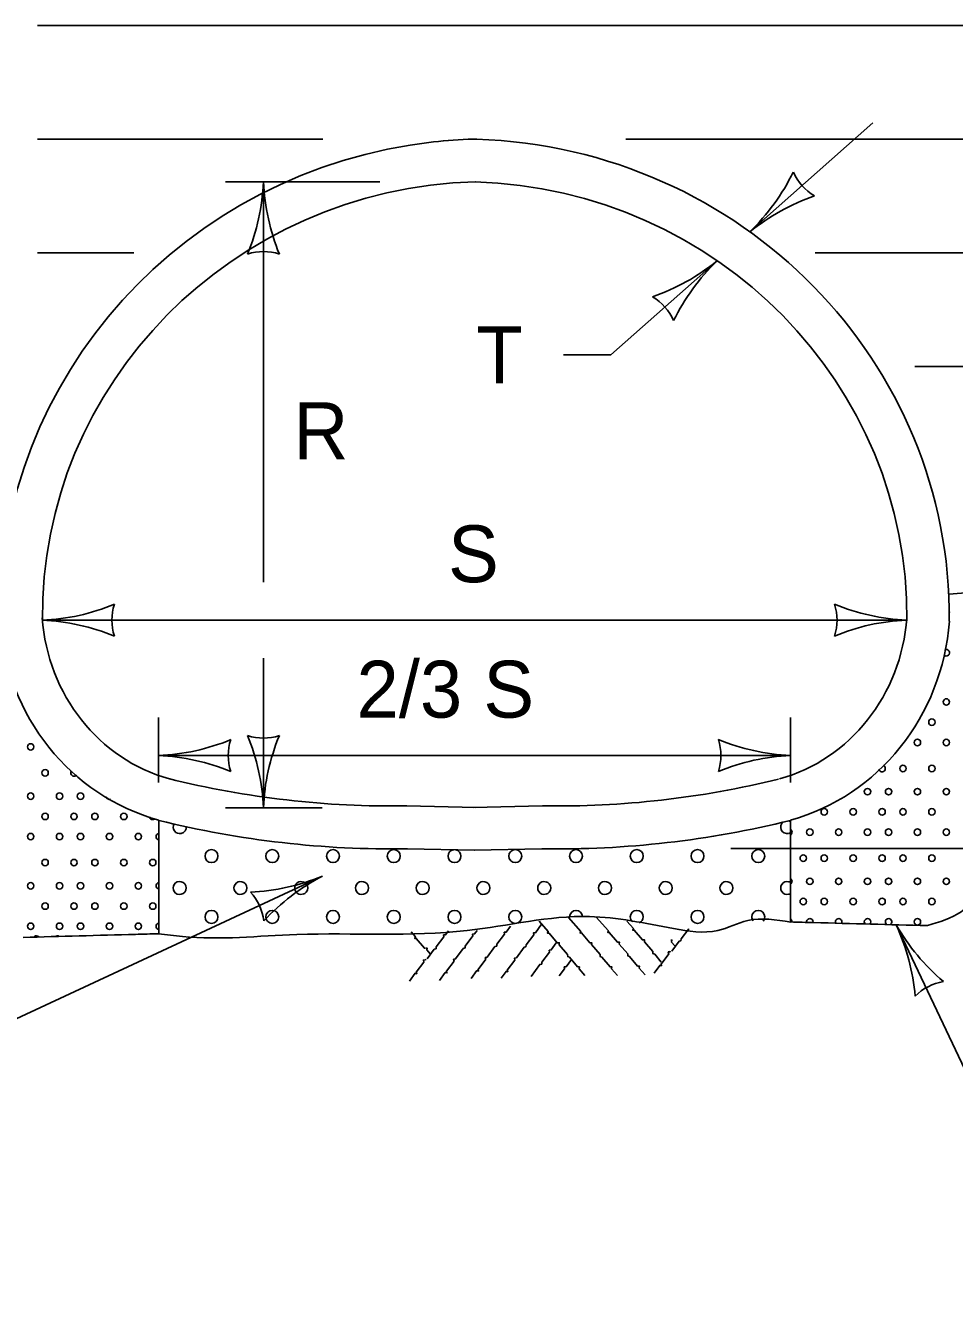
# Model space of a CAD drawing. Extents: x 49991.4 to 50021, y 49987.6 to 50011.4.
# Drawn here: x 50008.772 to 50009.753, y 49996.176 to 49997.512 of the extents above; entities that cross this region are included whole.
import ezdxf

# ---------------------------------------------------------------- set-up
doc = ezdxf.new("R2010")
doc.units = 0
for name, color, linetype in [('Level 1', 7, 'Continuous'), ('Level 2', 7, 'Continuous'), ('Level 3', 7, 'Continuous')]:
    doc.layers.add(name, color=color, linetype=linetype)

msp = doc.modelspace()

# ---------------------------------------------------------------- linework, layer by layer
at = {"layer": 'Level 1'}
for p, q in [((50008.785, 49997.5118), (50010.5816, 49997.5118)), ((50008.785, 49997.3918), (50009.0861, 49997.3918)), ((50009.2483, 49997.3918), (50009.2444, 49997.3918)), ((50009.4058, 49997.3918), (50010.4198, 49997.3918)), ((50008.785, 49997.2718), (50008.8867, 49997.2718)), ((50009.6053, 49997.2718), (50010.2692, 49997.2718)), ((50009.7106, 49997.1518), (50010.1883, 49997.1518)), ((50009.1745, 49996.6886), (50009.2473, 49996.6868)), ((50009.3179, 49996.6886), (50009.2445, 49996.6868)), ((50008.9129, 49996.6735), (50008.9129, 49996.5537)), ((50009.5793, 49996.6735), (50009.5793, 49996.5661)), ((50009.1751, 49996.6432), (50009.2462, 49996.6418)), ((50009.317, 49996.6432), (50009.2456, 49996.6418))]:
    msp.add_line(p, q, dxfattribs=at)
for points in [[(50009.3743, 49996.5712), (50009.3872, 49996.5567), (50009.3865, 49996.5551), (50009.3881, 49996.5551), (50009.3968, 49996.5448), (50009.3989, 49996.5449), (50009.3987, 49996.5428), (50009.4077, 49996.5324), (50009.4077, 49996.5304), (50009.4096, 49996.5298), (50009.4181, 49996.5194), (50009.4202, 49996.5194), (50009.4199, 49996.5173), (50009.426, 49996.5103)], [(50009.2425, 49996.5063), (50009.2485, 49996.5147), (50009.2502, 49996.5143), (50009.2498, 49996.5159), (50009.2579, 49996.5267), (50009.2574, 49996.5287), (50009.2594, 49996.529), (50009.2675, 49996.5401), (50009.2695, 49996.5406), (50009.2697, 49996.5426), (50009.2778, 49996.5532), (50009.2774, 49996.5552), (50009.2795, 49996.5553), (50009.2839, 49996.5615)], [(50009.2741, 49996.5067), (50009.2793, 49996.5139), (50009.281, 49996.5136), (50009.2806, 49996.5151), (50009.2887, 49996.5259), (50009.2882, 49996.528), (50009.2902, 49996.5283), (50009.2983, 49996.5393), (50009.3003, 49996.5399), (50009.3005, 49996.5418), (50009.3086, 49996.5525), (50009.3082, 49996.5545), (50009.3103, 49996.5546), (50009.3168, 49996.5636)], [(50009.3142, 49996.5668), (50009.3238, 49996.556), (50009.323, 49996.5543), (50009.3246, 49996.5544), (50009.3333, 49996.5441), (50009.3354, 49996.5441), (50009.3352, 49996.5421), (50009.3442, 49996.5317), (50009.3443, 49996.5296), (50009.3461, 49996.529), (50009.3547, 49996.5187), (50009.3567, 49996.5186), (50009.3564, 49996.5166), (50009.3625, 49996.5096)], [(50009.3451, 49996.5707), (50009.3581, 49996.556), (50009.3573, 49996.5544), (50009.3589, 49996.5545), (50009.3676, 49996.5441), (50009.3697, 49996.5442), (50009.3695, 49996.5422), (50009.3785, 49996.5317), (50009.3785, 49996.5297), (50009.3804, 49996.5291), (50009.389, 49996.5187), (50009.391, 49996.5187), (50009.3906, 49996.5167), (50009.3968, 49996.5096)], [(50009.4067, 49996.5669), (50009.4137, 49996.5591), (50009.4129, 49996.5574), (50009.4145, 49996.5575), (50009.4232, 49996.5472), (50009.4254, 49996.5472), (50009.4252, 49996.5452), (50009.4341, 49996.5348), (50009.4342, 49996.5327), (50009.4361, 49996.5321), (50009.4431, 49996.5236)], [(50009.4542, 49996.5354), (50009.4618, 49996.5457), (50009.4637, 49996.5463), (50009.4639, 49996.5483), (50009.472, 49996.5589), (50009.472, 49996.5589)], [(50009.179, 49996.5557), (50009.1837, 49996.5503), (50009.183, 49996.5487), (50009.1846, 49996.5487), (50009.1932, 49996.5384), (50009.1943, 49996.5385)], [(50009.1959, 49996.527), (50009.2035, 49996.5373), (50009.2055, 49996.5378), (50009.2057, 49996.5398), (50009.2138, 49996.5505), (50009.2134, 49996.5524), (50009.2155, 49996.5526), (50009.2186, 49996.5568)], [(50009.2091, 49996.5044), (50009.2151, 49996.5128), (50009.2169, 49996.5124), (50009.2165, 49996.514), (50009.2245, 49996.5247), (50009.224, 49996.5268), (50009.226, 49996.5271), (50009.2342, 49996.5382), (50009.2361, 49996.5387), (50009.2363, 49996.5407), (50009.2444, 49996.5513), (50009.244, 49996.5533), (50009.2461, 49996.5535), (50009.2488, 49996.5572)], [(50009.4532, 49996.5469), (50009.4542, 49996.5469), (50009.454, 49996.5449), (50009.4574, 49996.541)], [(50009.1949, 49996.5385), (50009.196, 49996.5385), (50009.1958, 49996.5365), (50009.1991, 49996.5326)], [(50009.3057, 49996.5087), (50009.3149, 49996.5212), (50009.3169, 49996.5217), (50009.3171, 49996.5237), (50009.3252, 49996.5343), (50009.3248, 49996.5363), (50009.3269, 49996.5365), (50009.3323, 49996.5439)], [(50009.4356, 49996.5121), (50009.4415, 49996.5203), (50009.4433, 49996.52), (50009.4429, 49996.5215), (50009.451, 49996.5323), (50009.4504, 49996.5344), (50009.4524, 49996.5347), (50009.4529, 49996.5354)], [(50009.1774, 49996.5036), (50009.1833, 49996.5119), (50009.185, 49996.5115), (50009.1846, 49996.5131), (50009.1927, 49996.5238), (50009.1921, 49996.5259), (50009.1942, 49996.5262), (50009.1947, 49996.5269)], [(50009.3353, 49996.5091), (50009.341, 49996.5167), (50009.3407, 49996.5187), (50009.3427, 49996.5188), (50009.3483, 49996.5265)]]:
    msp.add_lwpolyline(points, dxfattribs=at)
for centre in [(50009.7438, 49996.7981), (50009.7286, 49996.7768), (50009.7286, 49996.7768), (50009.7133, 49996.7554), (50009.7438, 49996.7554), (50008.7777, 49996.7507), (50009.6607, 49996.7035), (50009.6829, 49996.7035), (50009.7133, 49996.7035), (50009.7438, 49996.7035), (50008.7777, 49996.6988), (50008.8082, 49996.6988), (50008.8303, 49996.6988), (50008.7929, 49996.6774), (50008.7929, 49996.6774), (50008.8234, 49996.6774), (50008.8455, 49996.6774), (50008.876, 49996.6774), (50008.876, 49996.6774), (50009.615, 49996.6822), (50009.6455, 49996.6822), (50009.6455, 49996.6822), (50009.676, 49996.6822), (50009.6981, 49996.6822), (50009.7286, 49996.6822), (50009.7286, 49996.6822), (50009.5998, 49996.6608), (50009.6302, 49996.6608), (50009.6607, 49996.6608), (50009.6829, 49996.6608), (50009.7133, 49996.6608), (50009.7438, 49996.6608), (50008.7777, 49996.6561), (50008.8082, 49996.6561), (50008.8303, 49996.6561), (50008.8608, 49996.6561), (50008.8913, 49996.6561), (50009.5998, 49996.6089), (50009.6302, 49996.6089), (50009.6607, 49996.6089), (50009.6829, 49996.6089), (50009.7133, 49996.6089), (50009.7438, 49996.6089), (50008.7777, 49996.6042), (50008.8082, 49996.6042), (50008.8303, 49996.6042), (50008.8608, 49996.6042), (50008.8913, 49996.6042), (50008.7929, 49996.5828), (50008.7929, 49996.5828), (50008.8234, 49996.5828), (50008.8455, 49996.5828), (50008.876, 49996.5828), (50008.876, 49996.5828), (50008.9065, 49996.5828), (50009.5929, 49996.5876), (50009.615, 49996.5876), (50009.6455, 49996.5876), (50009.6455, 49996.5876), (50009.676, 49996.5876), (50009.6981, 49996.5876), (50009.7286, 49996.5876), (50009.7286, 49996.5876), (50008.7777, 49996.5615), (50008.8082, 49996.5615), (50008.8303, 49996.5615), (50008.8608, 49996.5615), (50008.8913, 49996.5615), (50009.7133, 49996.5662)]:
    msp.add_circle(centre, 0.00341, dxfattribs=at)
for centre, radius, start, end in [((50009.7438, 49996.8927), 0.00341, 337.7419, 24.4716), ((50009.7438, 49996.85), 0.00341, 225.166, 117.2024), ((50009.676, 49996.728), 0.00341, 0, 71.4249), ((50009.6981, 49996.728), 0.00341, 0, 180), ((50009.7286, 49996.728), 0.00341, 0, 180), ((50008.7929, 49996.7233), 0.00341, 0, 180), ((50008.7929, 49996.7232), 0.00341, 180, 0), ((50008.7929, 49996.7232), 0.00341, 180, 0), ((50008.8234, 49996.7233), 0.00341, 139.8568, 180), ((50008.8234, 49996.7232), 0.00341, 180, 321.6476), ((50009.676, 49996.7279), 0.00341, 194.081, 0), ((50009.6981, 49996.7279), 0.00341, 180, 0), ((50009.7286, 49996.7279), 0.00341, 180, 0), ((50009.7286, 49996.7279), 0.00341, 180, 0), ((50008.8608, 49996.6988), 0.00341, 190.2156, 289.4106), ((50008.9065, 49996.6774), 0.00341, 185.7827, 313.6596), ((50008.9349, 49996.666), 0.00682, 148.621, 282.921), ((50008.935, 49996.666), 0.00682, 282.921, 6.0281), ((50009.5759, 49996.666), 0.00682, 124.2955, 282.921), ((50009.5759, 49996.666), 0.00682, 77.079, 79.4798), ((50009.576, 49996.666), 0.00682, 60.5066, 77.079), ((50008.9134, 49996.6561), 0.00341, 99.1328, 260.8672), ((50009.576, 49996.666), 0.00682, 282.921, 299.4934), ((50009.5776, 49996.6608), 0.00341, 300.0634, 59.9366), ((50008.9685, 49996.6355), 0.00682, 0, 180), ((50009.0326, 49996.6355), 0.00682, 0, 180), ((50009.0967, 49996.6355), 0.00682, 0, 180), ((50009.1608, 49996.6355), 0.00682, 0, 180), ((50009.2249, 49996.6355), 0.00682, 100.2114, 180), ((50009.2249, 49996.6355), 0.00682, 0, 77.4448), ((50009.289, 49996.6355), 0.00682, 0, 180), ((50009.3531, 49996.6355), 0.00682, 0, 180), ((50009.4172, 49996.6355), 0.00682, 0, 180), ((50009.4813, 49996.6355), 0.00682, 0, 180), ((50009.5454, 49996.6355), 0.00682, 0, 180), ((50008.7929, 49996.6287), 0.00341, 0, 180), ((50008.7929, 49996.6286), 0.00341, 180, 0), ((50008.7929, 49996.6286), 0.00341, 180, 0), ((50008.8234, 49996.6287), 0.00341, 0, 180), ((50008.8234, 49996.6286), 0.00341, 180, 0), ((50008.8455, 49996.6287), 0.00341, 0, 180), ((50008.8455, 49996.6286), 0.00341, 180, 0), ((50008.876, 49996.6287), 0.00341, 0, 180), ((50008.876, 49996.6286), 0.00341, 180, 0), ((50008.876, 49996.6286), 0.00341, 180, 0), ((50008.9065, 49996.6287), 0.00341, 0, 180), ((50008.9065, 49996.6286), 0.00341, 180, 0), ((50008.9685, 49996.6355), 0.00682, 180, 0), ((50009.0326, 49996.6355), 0.00682, 180, 0), ((50009.0967, 49996.6355), 0.00682, 180, 0), ((50009.1608, 49996.6355), 0.00682, 180, 0), ((50009.2249, 49996.6355), 0.00682, 180, 0), ((50009.289, 49996.6355), 0.00682, 180, 0), ((50009.3531, 49996.6355), 0.00682, 180, 0), ((50009.4172, 49996.6355), 0.00682, 180, 0), ((50009.4813, 49996.6355), 0.00682, 180, 0), ((50009.5454, 49996.6355), 0.00682, 180, 0), ((50009.5929, 49996.6334), 0.00341, 0, 180), ((50009.5929, 49996.6333), 0.00341, 180, 0), ((50009.615, 49996.6334), 0.00341, 0, 180), ((50009.615, 49996.6333), 0.00341, 180, 0), ((50009.6455, 49996.6334), 0.00341, 0, 180), ((50009.6455, 49996.6333), 0.00341, 180, 0), ((50009.6455, 49996.6333), 0.00341, 180, 0), ((50009.676, 49996.6334), 0.00341, 0, 180), ((50009.676, 49996.6333), 0.00341, 180, 0), ((50009.6981, 49996.6334), 0.00341, 0, 180), ((50009.6981, 49996.6333), 0.00341, 180, 0), ((50009.7286, 49996.6334), 0.00341, 0, 180), ((50009.7286, 49996.6333), 0.00341, 180, 0), ((50009.7286, 49996.6333), 0.00341, 180, 0), ((50009.5776, 49996.6089), 0.00341, 300.0634, 59.9366), ((50008.9134, 49996.6042), 0.00341, 99.1328, 260.8672), ((50008.9349, 49996.6019), 0.00682, 77.079, 282.921), ((50008.935, 49996.6019), 0.00682, 282.921, 77.079), ((50008.999, 49996.6019), 0.00682, 77.079, 282.921), ((50008.9991, 49996.6019), 0.00682, 282.921, 77.079), ((50009.0631, 49996.6019), 0.00682, 77.079, 282.921), ((50009.0632, 49996.6019), 0.00682, 282.921, 77.079), ((50009.1272, 49996.6019), 0.00682, 77.079, 282.921), ((50009.1273, 49996.6019), 0.00682, 282.921, 77.079), ((50009.1913, 49996.6019), 0.00682, 77.079, 282.921), ((50009.1914, 49996.6019), 0.00682, 282.921, 77.079), ((50009.2554, 49996.6019), 0.00682, 77.079, 282.921), ((50009.2555, 49996.6019), 0.00682, 282.921, 77.079), ((50009.3195, 49996.6019), 0.00682, 77.079, 282.921), ((50009.3196, 49996.6019), 0.00682, 282.921, 77.079), ((50009.3836, 49996.6019), 0.00682, 77.079, 282.921), ((50009.3837, 49996.6019), 0.00682, 282.921, 77.079), ((50009.4477, 49996.6019), 0.00682, 77.079, 282.921), ((50009.4478, 49996.6019), 0.00682, 282.921, 77.079), ((50009.5118, 49996.6019), 0.00682, 77.079, 282.921), ((50009.5119, 49996.6019), 0.00682, 282.921, 77.079), ((50009.5759, 49996.6019), 0.00682, 77.079, 282.921), ((50009.576, 49996.6019), 0.00682, 60.5066, 77.079), ((50009.576, 49996.6019), 0.00682, 282.921, 299.4934), ((50008.9685, 49996.5714), 0.00682, 0, 180), ((50008.9685, 49996.5714), 0.00682, 180, 0), ((50009.0326, 49996.5714), 0.00682, 0, 180), ((50009.0326, 49996.5714), 0.00682, 180, 0), ((50009.0967, 49996.5714), 0.00682, 0, 180), ((50009.0967, 49996.5714), 0.00682, 180, 0), ((50009.1608, 49996.5714), 0.00682, 0, 180), ((50009.1608, 49996.5714), 0.00682, 180, 0), ((50009.2249, 49996.5714), 0.00682, 0, 180), ((50009.2249, 49996.5714), 0.00682, 180, 0), ((50009.289, 49996.5714), 0.00682, 0, 180), ((50009.289, 49996.5714), 0.00682, 180, 0), ((50009.3531, 49996.5714), 0.00682, 2.9356, 180), ((50009.3531, 49996.5714), 0.00682, 180, 182.7942), ((50009.4172, 49996.5714), 0.00682, 0, 180), ((50009.4172, 49996.5714), 0.00682, 180, 227.8656), ((50009.4172, 49996.5714), 0.00682, 290.6259, 0), ((50009.4813, 49996.5714), 0.00682, 0, 180), ((50009.4813, 49996.5714), 0.00682, 180, 0), ((50009.5454, 49996.5714), 0.00682, 0, 180), ((50009.5454, 49996.5714), 0.00682, 180, 216.2107), ((50009.5454, 49996.5714), 0.00682, 319.8928, 0), ((50008.9134, 49996.5615), 0.00341, 99.1328, 260.8672), ((50009.5776, 49996.5662), 0.00341, 357.5996, 59.9366), ((50009.5998, 49996.5662), 0.00341, 346.5723, 190.2224), ((50009.6302, 49996.5662), 0.00341, 331.9636, 204.9636), ((50009.6607, 49996.5662), 0.00341, 315.1755, 221.7599), ((50009.6829, 49996.5662), 0.00341, 299.2273, 237.7119), ((50008.7838, 49996.548), 0.00341, 40.9345, 142.1157), ((50008.8059, 49996.548), 0.00341, 55.4204, 127.6355)]:
    msp.add_arc(centre, radius, start, end, dxfattribs=at)
for centre, major_axis, ratio, start_param, end_param in [((50009.2605, 49996.8888), (-0.5152, -0.0149), 0.976362, 4.796646, 6.264407), ((50009.2605, 49996.8888), (-0.5152, -0.0149), 0.976362, 4.715363, 4.796646), ((50009.2606, 49996.8888), (-0.5152, -0.0149), 0.976362, 4.715363, 4.796646), ((50009.2315, 49996.8888), (0.5152, -0.0149), 0.976362, 0.018778, 1.566912), ((50009.2605, 49996.8888), (-0.4703, -0.0136), 0.9741, 4.713164, 6.264407), ((50009.2317, 49996.8888), (0.4703, -0.0136), 0.9741, 0.018778, 1.566912), ((50008.9699, 49996.9013), (0, -0.2355), 0.956933, 4.789023, 6.027364), ((50008.9697, 49996.9013), (0, -0.1905), 0.946758, 4.789023, 6.027407), ((50009.5223, 49996.9013), (0, -0.1905), 0.946758, 0.255726, 1.494162), ((50009.5223, 49996.9013), (0, -0.2355), 0.956933, 0.255933, 1.494162), ((50009.1591, 49997.7592), (0, -1.0708), 0.955439, 6.050463, 6.2982), ((50009.3332, 49997.7592), (0, -1.0708), 0.955439, 6.26817, 6.513619), ((50009.1591, 49997.7592), (0, -1.1161), 0.956933, 6.050534, 6.2982), ((50009.3331, 49997.7592), (0, -1.1161), 0.956933, 6.26817, 6.515885)]:
    msp.add_ellipse(centre, major_axis=major_axis, ratio=ratio, start_param=start_param, end_param=end_param, dxfattribs=at)
for points in [[(50010.2332, 49996.9201), (50010.1311, 49996.9099), (50009.9674, 49996.9146), (50009.8842, 49996.9099), (50009.8177, 49996.9146), (50009.7464, 49996.9118)], [(50009.7238, 49996.5622), (50009.7593, 49996.5769), (50009.7838, 49996.6038), (50009.8288, 49996.6693)], [(50008.9127, 49996.5537), (50008.9379, 49996.5506), (50009.0584, 49996.5528), (50009.2382, 49996.557), (50009.3672, 49996.5718), (50009.456, 49996.5591), (50009.5026, 49996.557), (50009.5343, 49996.5675), (50009.5796, 49996.566)], [(50009.5796, 49996.5661), (50009.6041, 49996.5654), (50009.7238, 49996.5622)], [(50008.7698, 49996.5498), (50008.8882, 49996.553), (50008.9127, 49996.5537)]]:
    msp.add_spline(points, degree=3, dxfattribs=at)
at = {"layer": 'Level 3'}
for p, q in [((50009.5366, 49997.294), (50009.6664, 49997.4089)), ((50009.1462, 49997.3466), (50008.9832, 49997.3466)), ((50009.0233, 49996.9244), (50009.0233, 49997.3466)), ((50009.3898, 49997.1642), (50009.5019, 49997.2634)), ((50009.3898, 49997.1642), (50009.34, 49997.1642)), ((50009.7469, 49996.8833), (50009.7469, 49996.8929)), ((50009.7019, 49996.8844), (50008.79, 49996.8844)), ((50009.0233, 49996.6866), (50009.0233, 49996.8444)), ((50008.9127, 49996.7132), (50008.9127, 49996.7816)), ((50009.5793, 49996.7132), (50009.5793, 49996.7816)), ((50009.5793, 49996.7416), (50008.9127, 49996.7416)), ((50009.0853, 49996.6866), (50008.9832, 49996.6866)), ((50010.3763, 49996.6435), (50009.5165, 49996.6435)), ((50008.2668, 49996.2328), (50009.0856, 49996.6145)), ((50009.6943, 49996.5555), (50009.8743, 49996.1761))]:
    msp.add_line(p, q, dxfattribs=at)
for centre, radius, start, end in [((50008.8011, 49997.3558), 0.2223, 337.456, 357.6395), ((50009.256, 49997.3581), 0.233, 182.8273, 202.0772), ((50009.3737, 49997.4607), 0.233, 314.328, 333.5778), ((50009.6326, 49997.379), 0.0548, 203.6395, 239.3618), ((50009.6769, 49997.1216), 0.2223, 108.9567, 129.1402), ((50009.0233, 49997.2184), 0.0548, 72.1388, 107.8612), ((50009.3616, 49997.4358), 0.2223, 288.9567, 309.1402), ((50009.6647, 49997.0967), 0.233, 134.328, 153.5778), ((50009.4059, 49997.1784), 0.0548, 23.6395, 59.3618), ((50008.7808, 49997.1065), 0.2223, 272.3605, 292.544), ((50008.9182, 49996.8844), 0.0548, 162.1388, 197.8612), ((50009.5737, 49996.8844), 0.0548, 342.1388, 17.8612), ((50009.7134, 49997.1171), 0.233, 247.9228, 267.1727), ((50008.7785, 49996.6517), 0.233, 67.9228, 87.1727), ((50009.711, 49996.6623), 0.2223, 92.3605, 112.544), ((50008.9035, 49996.9637), 0.2223, 272.3605, 292.544), ((50009.0409, 49996.7416), 0.0548, 162.1388, 197.8612), ((50009.0233, 49996.8148), 0.0548, 252.1388, 287.8612), ((50008.7906, 49996.6751), 0.233, 2.8273, 22.0772), ((50009.2454, 49996.6774), 0.2223, 157.456, 177.6395), ((50009.4511, 49996.7416), 0.0548, 342.1388, 17.8612), ((50009.5908, 49996.9743), 0.233, 247.9228, 267.1727), ((50008.9012, 49996.5089), 0.233, 67.9228, 87.1727), ((50009.5885, 49996.5195), 0.2223, 92.3605, 112.544), ((50009, 49996.8197), 0.2223, 272.448, 292.6315), ((50009.1943, 49996.4084), 0.233, 117.8193, 137.0691), ((50008.9694, 49996.5603), 0.0548, 7.1308, 42.8532), ((50009.8842, 49996.673), 0.2223, 209.6331, 229.8166), ((50009.4789, 49996.4666), 0.233, 5.1954, 24.4453), ((50009.7497, 49996.4491), 0.0548, 99.4114, 135.1338)]:
    msp.add_arc(centre, radius, start, end, dxfattribs=at)

# ---------------------------------------------------------------- texts
at = {"layer": 'Level 2'}
for s, p in [('T', (50009.248, 49997.1342)), ('R', (50009.055, 49997.0542)), ('S', (50009.2181, 49996.9244)), ('2/3 S', (50009.1215, 49996.7816))]:
    msp.add_text(s, height=0.06, dxfattribs=at).set_placement(p)

doc.saveas('drawing.dxf')
